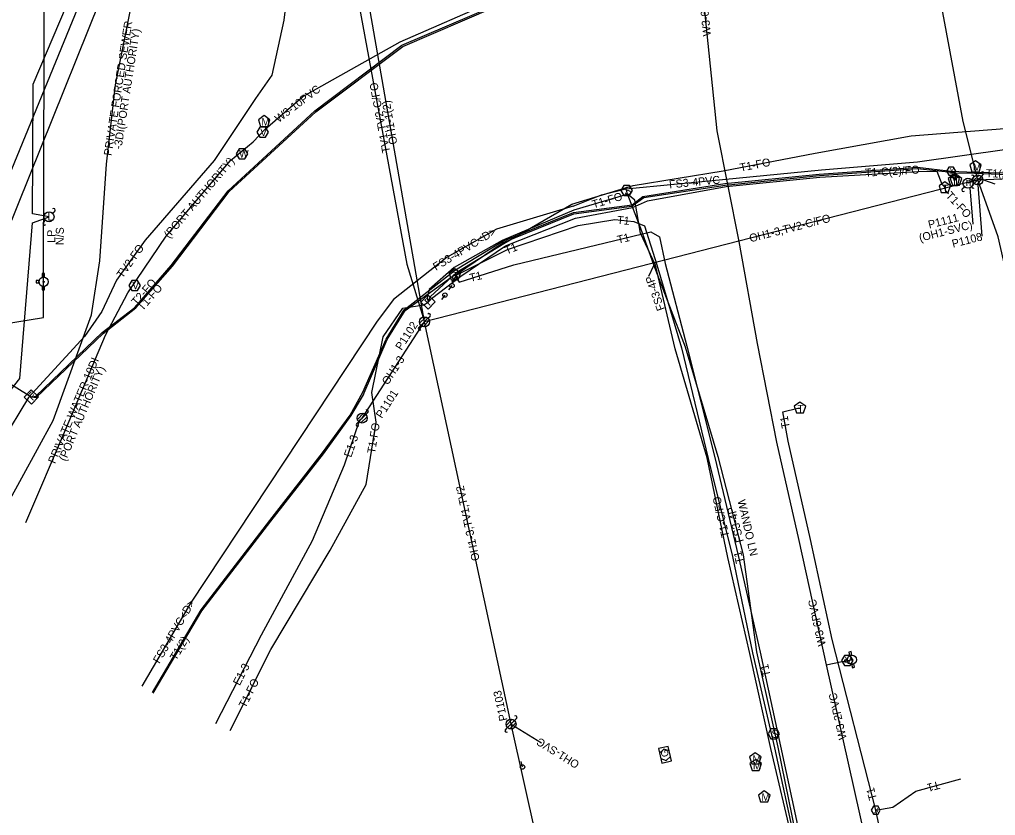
# Model space of a CAD drawing. Extents: x 2336688 to 2352634, y 362473 to 369571.
# Drawn here: x 2345394.9 to 2345882.8, y 366711.7 to 367109.6 of the extents above; entities that cross this region are included whole.
import ezdxf

# ---------------------------------------------------------------- set-up
doc = ezdxf.new("R2010")
doc.units = 0
for name, color, linetype in [('RD_EX_DV_Prop', 7, 'Continuous'), ('RD_EX_DV_TX_Prop', 7, 'Continuous'), ('RD_EX_RW', 7, 'Continuous'), ('RD_EX_RW_TX', 7, 'Continuous'), ('RD_HC_Data_Tic', 7, 'Continuous'), ('RD_PD_CstnLmt', 7, 'Continuous'), ('RD_PD_Final_TrvlWay', 7, 'Continuous'), ('RD_PD_PatLn4', 7, 'Continuous'), ('RD_SHT_ShtClip', 7, 'Continuous'), ('RD_Sketch1', 7, 'Continuous'), ('RD_Sketch2', 7, 'Continuous'), ('RD_Sketch5', 7, 'Continuous'), ('RD_TX_Misc1', 7, 'Continuous')]:
    doc.layers.add(name, color=color, linetype=linetype)

# ---------------------------------------------------------------- blocks, each defined once
blk = doc.blocks.new('GW')
at = {"layer": 'RD_HC_Data_Tic'}
blk.add_line((0, 0), (0, 5), dxfattribs=at)
blk.add_circle((0, 0), 2, dxfattribs=at)

msp = doc.modelspace()

# ---------------------------------------------------------------- linework, layer by layer
at = {"layer": 'RD_EX_DV_TX_Prop'}
for p, q in [((2345876.09, 367001.24), (2345874.09, 367026.87)), ((2345871.56, 367007.24), (2345870.14, 367025.46))]:
    msp.add_line(p, q, dxfattribs=at)
at = {"layer": 'RD_EX_RW_TX'}
msp.add_line((2345399.69, 366921.53), (2345364.16, 366943.34), dxfattribs=at)
for points in [[(2345400.86, 367609.96), (2345400.86, 367580.52), (2345476.19, 367221.38), (2345364.16, 366943.34), (2345117.95, 366720.57)], [(2345560.36, 367158.37), (2345561.17, 367156.84), (2345555.2, 367151.92), (2345529.41, 367128.95), (2345527.05, 367109.15), (2345521, 367081.68), (2345512.82, 367070.16), (2345492.13, 367039.11), (2345457.71, 366999.28), (2345443.39, 366979.23), (2345436.01, 366963.6), (2345427.31, 366951.13), (2345399.42, 366920.61), (2345372.17, 366875.98), (2345340.52, 366834.69)], [(2345400.81, 366920.91), (2345403.21, 366920.71), (2345436.7, 366952.69), (2345453.09, 366965.46), (2345471.44, 366986.29), (2345499.66, 367023.61), (2345543.05, 367063.34), (2345586.52, 367096.12), (2345632.95, 367115.99), (2345683.75, 367128.36), (2345734.17, 367135.46), (2345786.21, 367138.11), (2345835, 367141.95), (2345884.47, 367148.28)], [(2345399.69, 366921.53), (2345400.81, 366920.91), (2345403.09, 366921.35), (2345436.25, 366953.11), (2345452.55, 366965.66), (2345470.76, 366986.63), (2345499.17, 367023.99), (2345542.57, 367063.95), (2345586.06, 367096.71), (2345632.54, 367116.51), (2345683.64, 367129.17), (2345734.05, 367136.11), (2345786.05, 367139.04), (2345834.85, 367142.6), (2345856.07, 367145.42), (2345857.04, 367146.79)], [(2345500.17, 366754.27), (2345520.52, 366794.66), (2345550.15, 366844.34), (2345568.15, 366877.1), (2345573.13, 366908.35), (2345571.01, 366923.07), (2345576.64, 366951.02), (2345586.5, 366965.25), (2345596.98, 366967.01), (2345599.12, 366968.34), (2345600.17, 366970.98), (2345613.47, 366983.28), (2345637.02, 366997.67), (2345671.07, 367017.26), (2345701.71, 367026.64), (2345746.61, 367033.87), (2345792.68, 367042.78), (2345840.6, 367051.43), (2345887.37, 367055.13)], [(2345461.45, 366773.12), (2345485.72, 366814.45), (2345520.05, 366859.13), (2345546.44, 366892.9), (2345560.12, 366911.85), (2345566.57, 366923.25), (2345578.21, 366949.73), (2345587.16, 366964.52), (2345612.86, 366984.47), (2345636.46, 366998.7), (2345671.8, 367013.17), (2345701.1, 367016.89), (2345706.53, 367021.09), (2345747.51, 367027.63), (2345794.71, 367032.18), (2345843.88, 367035.75), (2345860.6, 367033.82), (2345872.36, 367033.23), (2345893.42, 367032.83)], [(2345461.79, 366772.92), (2345486.1, 366814.09), (2345520.53, 366858.85), (2345546.93, 366892.43), (2345560.65, 366911.63), (2345566.89, 366921.96), (2345567.23, 366922.93), (2345578.65, 366949.6), (2345587.63, 366964.05), (2345611.13, 366981.08), (2345612.48, 366981.87), (2345613.41, 366982.24), (2345636.74, 366998.18), (2345672.09, 367012.44), (2345701.07, 367016.24), (2345707.06, 367020.61), (2345747.66, 367026.84), (2345794.76, 367031.59), (2345843.89, 367035.01), (2345862.09, 367033.07), (2345862.66, 367029.98), (2345863.05, 367029.2), (2345863.18, 367029.93), (2345862.88, 367032.97), (2345872.26, 367032.7), (2345893.38, 367031.97)], [(2345599.12, 366968.34), (2345600.85, 366970.06), (2345615.49, 366981.23), (2345637.9, 366996.5), (2345672.85, 367010.22), (2345701.31, 367015.58), (2345708.79, 367018.93), (2345748.08, 367026.1), (2345794.99, 367030.74), (2345843.92, 367033.65), (2345853.44, 367033.69), (2345855.93, 367027.34), (2345856.96, 367026.23), (2345857.46, 367025.46), (2345857.67, 367024.28), (2345859.32, 367022.48)], [(2345860.6, 367033.82), (2345861.81, 367030.13), (2345861.99, 367029.09)], [(2345873.97, 367029.36), (2345874.41, 367030.21), (2345882.47, 367027.46)], [(2345750.74, 366593.81), (2345793.71, 366604.91), (2345793.6, 366606.53), (2345795.31, 366607.4), (2345799.9, 366613.11), (2345800.37, 366616.85), (2345793.67, 366642.96), (2345781.73, 366697.86), (2345770.41, 366745.28), (2345760, 366792.61), (2345749.03, 366840.68), (2345738.69, 366890.47), (2345722.69, 366945), (2345712.84, 366986.7), (2345705.27, 367002.76), (2345702.43, 367019.22), (2345698.82, 367022.22), (2345694.02, 367020.8), (2345671.99, 367014.3), (2345636.25, 366999.09), (2345612.16, 366985.56), (2345599.72, 366974.65), (2345598.65, 366970.42), (2345599.12, 366968.34)], [(2345612.48, 366981.87), (2345613.56, 366981.96), (2345638.84, 366994.67), (2345674.13, 367006.57), (2345692.49, 367009.56), (2345702.05, 367008.67), (2345707.41, 367006.4), (2345713.56, 366986.96), (2345725.76, 366945.42), (2345739.18, 366890.21), (2345751.26, 366841.1), (2345761.25, 366792.95), (2345772.3, 366745.59), (2345783.61, 366693.46), (2345794.68, 366643.14), (2345807.85, 366590.13), (2345818.75, 366543.34)], [(2345612.48, 366981.87), (2345612.77, 366981.03), (2345614.7, 366978.36), (2345642.03, 366986.89), (2345710.46, 367003.43), (2345714.81, 367000.95), (2345717.61, 366987.66), (2345728.58, 366946.26), (2345742.57, 366890.63), (2345754.16, 366841.7), (2345765.23, 366793.37), (2345775.39, 366746.33), (2345786.64, 366693.71), (2345797.72, 366643.63), (2345808.54, 366590.2), (2345821.21, 366544.02)], [(2345856.53, 366551.35), (2345848.37, 366592.23), (2345848.01, 366593.78), (2345854.54, 366595.47), (2345855.72, 366595.54), (2345853.67, 366595.82), (2345847.63, 366594.93), (2345846.69, 366600.45), (2345836.4, 366650.92), (2345822.92, 366714.36), (2345801.14, 366799.7), (2345790.37, 366849.7), (2345779.17, 366898.83), (2345776.52, 366913.54), (2345784.01, 366915.26), (2345785.05, 366915.36)], [(2345822.92, 366714.36), (2345831.44, 366715.85), (2345843.03, 366723.83), (2345865.4, 366730.06)]]:
    msp.add_lwpolyline(points, dxfattribs=at)
for points in [[(2345862.91, 367033.82), (2345861.76, 367035.82), (2345859.45, 367035.82), (2345858.29, 367033.82), (2345859.45, 367031.82), (2345861.76, 367031.82)], [(2345861.99, 367032.09), (2345859.14, 367030.02), (2345860.23, 367026.66), (2345863.76, 367026.66), (2345864.85, 367030.02)], [(2345863.05, 367032.2), (2345860.2, 367030.13), (2345861.29, 367026.78), (2345864.82, 367026.78), (2345865.91, 367030.13)], [(2345857.46, 367028.46), (2345854.6, 367026.39), (2345855.69, 367023.03), (2345859.22, 367023.03), (2345860.31, 367026.39)], [(2345612.48, 366984.87), (2345609.63, 366982.8), (2345610.72, 366979.44), (2345614.24, 366979.44), (2345615.33, 366982.8)], [(2345599.06, 366971.88), (2345595.59, 366968.28), (2345599.19, 366964.81), (2345602.66, 366968.41)], [(2345400.74, 366924.44), (2345397.28, 366920.84), (2345400.88, 366917.38), (2345404.34, 366920.98)], [(2345785.05, 366918.36), (2345782.2, 366916.29), (2345783.29, 366912.94), (2345786.82, 366912.94), (2345787.91, 366916.29)], [(2345825.23, 366714.36), (2345824.07, 366716.36), (2345821.76, 366716.36), (2345820.61, 366714.36), (2345821.76, 366712.36), (2345824.07, 366712.36)]]:
    msp.add_lwpolyline(points, close=True, dxfattribs=at)
at = {"layer": 'RD_HC_Data_Tic'}
for p, q in [((2345871.55, 367028.72), (2345874.62, 367031.78)), ((2345872.2, 367027.6), (2345875.74, 367031.13)), ((2345875.74, 367031.13), (2345876.8, 367032.19)), ((2345866.21, 367024.88), (2345867.27, 367025.94)), ((2345870.81, 367029.47), (2345871.87, 367030.53)), ((2345871.14, 367026.54), (2345872.2, 367027.6)), ((2345873.32, 367026.95), (2345876.38, 367030.01)), ((2345411.42, 367012.73), (2345412.48, 367013.79)), ((2345406.83, 367008.13), (2345407.89, 367009.2)), ((2345594.89, 366957.8), (2345597.95, 366960.86)), ((2345595.54, 366956.68), (2345599.07, 366960.21)), ((2345596.66, 366956.03), (2345599.72, 366959.09)), ((2345599.07, 366960.21), (2345600.13, 366961.27)), ((2345594.48, 366955.61), (2345595.54, 366956.68)), ((2345563.82, 366909.71), (2345566.88, 366912.77)), ((2345564.47, 366908.59), (2345568, 366912.12)), ((2345565.59, 366907.94), (2345568.65, 366911)), ((2345568, 366912.12), (2345569.06, 366913.18)), ((2345563.41, 366907.53), (2345564.47, 366908.59)), ((2345638.18, 366756.75), (2345641.24, 366759.81)), ((2345638.83, 366755.63), (2345642.36, 366759.17)), ((2345639.95, 366754.98), (2345643.01, 366758.05)), ((2345642.36, 366759.17), (2345643.42, 366760.23)), ((2345637.77, 366754.57), (2345638.83, 366755.63))]:
    msp.add_line(p, q, dxfattribs=at)
for centre in [(2345873.97, 367029.36), (2345869.04, 367027.71), (2345409.65, 367010.96), (2345597.31, 366958.44), (2345566.24, 366910.36), (2345640.6, 366757.4)]:
    msp.add_circle(centre, 2.5, dxfattribs=at)
for centre, start, end in [((2345871.34, 367031.06), 315, 135), ((2345876.27, 367032.72), 315, 135), ((2345871.67, 367026.01), 135, 315), ((2345866.74, 367024.35), 135, 315), ((2345411.95, 367014.32), 315, 135), ((2345407.36, 367007.6), 135, 315), ((2345599.6, 366961.8), 315, 135), ((2345595.01, 366955.08), 135, 315), ((2345568.53, 366913.71), 315, 135), ((2345563.94, 366907), 135, 315), ((2345642.89, 366760.76), 315, 135), ((2345638.3, 366754.04), 135, 315)]:
    msp.add_arc(centre, 0.75, start, end, dxfattribs=at)
at = {"layer": 'RD_PD_Final_TrvlWay'}
for points in [[(2345391.05, 367609.96), (2345391.05, 367588.26), (2345470.9, 367229.85), (2345354.8, 366946.71), (2345105.35, 366734.78)], [(2345370.88, 366899.63), (2345394.98, 366930.11), (2345401.39, 367007.89), (2345409.65, 367010.96), (2345401.4, 367012.45), (2345401.49, 367040.33), (2345401.67, 367077.29), (2345441.14, 367170.24)], [(2345493.08, 366757.65), (2345515.92, 366802), (2345541.44, 366849.18), (2345557.44, 366887), (2345565.1, 366909.55), (2345566.24, 366910.36)]]:
    msp.add_lwpolyline(points, dxfattribs=at)
at = {"layer": 'RD_SHT_ShtClip'}
for p, q in [((2345597.31, 366958.44), (2345562.51, 367157.67)), ((2345873.97, 367029.36), (2346156.71, 367042.77)), ((2345873.97, 367029.36), (2345597.31, 366958.44)), ((2345873.97, 367029.36), (2345869.04, 367027.71)), ((2345566.24, 366910.36), (2345597.31, 366958.44)), ((2345640.6, 366757.4), (2345597.31, 366958.44)), ((2345680.37, 366580.27), (2345640.6, 366757.4)), ((2345640.6, 366757.4), (2345655.83, 366747.95))]:
    msp.add_line(p, q, dxfattribs=at)
for points in [[(2345873.97, 367029.36), (2345866.69, 367058.52), (2345835.13, 367227.45), (2345831.39, 367257.27)], [(2345560.36, 367158.37), (2345562.49, 367128.3), (2345588.55, 366987.28), (2345597.31, 366958.44)], [(2345936.7, 366754.94), (2345933.52, 366784.99), (2345884.16, 367000.92), (2345873.97, 367029.36)]]:
    msp.add_lwpolyline(points, dxfattribs=at)
at = {"layer": 'RD_Sketch1'}
msp.add_line((2345709.53, 366981.32), (2345711.96, 366986.54), dxfattribs=at)
at = {"layer": 'RD_Sketch2'}
for p, q in [((2345406.29, 366982.54), (2345406.28, 366980.68)), ((2345407.44, 366982.54), (2345406.29, 366982.54)), ((2345407.44, 366980.72), (2345407.44, 366982.54)), ((2345404.72, 366979.1), (2345403.22, 366979.11)), ((2345403.22, 366979.11), (2345403.22, 366977.95)), ((2345403.22, 366977.95), (2345404.69, 366977.95)), ((2345406.27, 366976.26), (2345406.26, 366974.46)), ((2345406.26, 366974.46), (2345407.42, 366974.46)), ((2345407.42, 366974.46), (2345407.42, 366976.21)), ((2345810.61, 366793.68), (2345809.48, 366793.43)), ((2345809.48, 366793.43), (2345809.89, 366791.61)), ((2345811.01, 366791.91), (2345810.61, 366793.68)), ((2345808.72, 366789.72), (2345807.26, 366789.39)), ((2345807.26, 366789.39), (2345807.51, 366788.27)), ((2345807.51, 366788.27), (2345808.95, 366788.59)), ((2345810.87, 366787.29), (2345811.26, 366785.54)), ((2345812.39, 366785.79), (2345812, 366787.51)), ((2345811.26, 366785.54), (2345812.39, 366785.79))]:
    msp.add_line(p, q, dxfattribs=at)
for points in [[(2345109.82, 366912.24), (2345406.89, 366960.68), (2345406.94, 366978.47), (2345408.67, 367610.14)], [(2345398.01, 366858.08), (2345417.9, 366904.52), (2345437.85, 366951.84), (2345449.04, 366972.91), (2345453.48, 366979.61), (2345468.15, 367001.19), (2345500.41, 367039.08), (2345511.67, 367048.37), (2345517.71, 367054.69), (2345536.56, 367071.08), (2345585.14, 367098.45), (2345633.32, 367119.57), (2345683.1, 367133.89), (2345734.03, 367142.31), (2345784.94, 367146.49), (2345833.73, 367148.15), (2345883.62, 367150.82)], [(2345734.3, 367142.33), (2345734.6, 367138.65), (2345736.14, 367125.25), (2345743.53, 367053.85), (2345754.56, 366998.53), (2345763.65, 366947.65), (2345773.38, 366898.37), (2345784.57, 366849.11), (2345798.12, 366787.04), (2345817.62, 366699.96), (2345828.5, 366650.59), (2345839.82, 366600.83), (2345850.62, 366551.62)], [(2345798.12, 366787.04), (2345805.39, 366788.58), (2345809.76, 366789.38), (2345811.03, 366789.6)]]:
    msp.add_lwpolyline(points, dxfattribs=at)
for points in [[(2345517.2, 367061.57), (2345514.3, 367059.46), (2345515.41, 367056.05), (2345518.99, 367056.05), (2345520.1, 367059.46)], [(2345519.33, 367053.2), (2345517.88, 367055.7), (2345515, 367055.7), (2345513.55, 367053.2), (2345515, 367050.7), (2345517.88, 367050.7)], [(2345508.97, 367042.41), (2345507.53, 367044.9), (2345504.64, 367044.9), (2345503.2, 367042.41), (2345504.64, 367039.91), (2345507.53, 367039.91)], [(2345872.81, 367038.97), (2345869.91, 367036.86), (2345871.02, 367033.45), (2345874.61, 367033.45), (2345875.71, 367036.86)], [(2345455.33, 366976.65), (2345453.89, 366979.15), (2345451, 366979.15), (2345449.56, 366976.65), (2345451, 366974.15), (2345453.89, 366974.15)], [(2345811.62, 366789.24), (2345810.17, 366791.74), (2345807.29, 366791.74), (2345805.84, 366789.24), (2345807.29, 366786.74), (2345810.17, 366786.74)], [(2345762.7, 366743.07), (2345759.8, 366740.96), (2345760.91, 366737.55), (2345764.49, 366737.55), (2345765.6, 366740.96)], [(2345762.93, 366739.76), (2345760.03, 366737.65), (2345761.14, 366734.24), (2345764.72, 366734.24), (2345765.83, 366737.65)], [(2345767.19, 366724.03), (2345764.29, 366721.93), (2345765.39, 366718.52), (2345768.98, 366718.52), (2345770.09, 366721.93)]]:
    msp.add_lwpolyline(points, close=True, dxfattribs=at)
for centre, radius in [((2345406.94, 366978.47), 2.31), ((2345406.94, 366978.47), 0.289), ((2345811.03, 366789.6), 2.31), ((2345811.03, 366789.6), 0.289)]:
    msp.add_circle(centre, radius, dxfattribs=at)
for centre, start, end in [((2345406.94, 366978.47), 164.064, 193.0312), ((2345406.94, 366978.47), 77.5034, 106.4797), ((2345406.94, 366978.47), 253.1571, 282.1335), ((2345811.03, 366789.6), 90.4016, 119.378), ((2345811.03, 366789.6), 176.9622, 205.9294), ((2345811.03, 366789.6), 266.0554, 295.0317)]:
    msp.add_arc(centre, 2.31, start, end, dxfattribs=at)
at = {"layer": 'RD_Sketch5'}
for points in [[(2345388.31, 366866.23), (2345411.68, 366909.13), (2345430.85, 366961.88), (2345435.05, 366988.91), (2345438.45, 367037.33), (2345442.85, 367076.95), (2345451.04, 367117.69)], [(2345671.65, 367016.28), (2345685.91, 367021.93), (2345698.01, 367025), (2345746.34, 367029.53), (2345795.81, 367034.45), (2345843.73, 367038.37), (2345888.51, 367044.73), (2345943.3, 367049.45), (2346003.21, 367051.06), (2346044.44, 367048.09), (2346104.33, 367049.8), (2346147.49, 367056.12), (2346190.02, 367059.03), (2346247.96, 367065.62), (2346294.65, 367066.48), (2346342.24, 367070.89), (2346392.92, 367073.62), (2346445.33, 367080.3)], [(2345698.01, 367025), (2345698.55, 367022.93), (2345705.27, 367005.26), (2345711.96, 366986.54), (2345727.6, 366946), (2345743.93, 366891.21), (2345756.59, 366841.99), (2345763.32, 366793.48), (2345773.98, 366745.9), (2345784.68, 366693.55), (2345796.23, 366643.51), (2345807.18, 366590.01), (2345819.85, 366543.64)], [(2345671.65, 367016.28), (2345633.43, 367004.74), (2345608.63, 366990.82), (2345581.94, 366969.69), (2345573.77, 366958.77), (2345480.4, 366817.86), (2345456.01, 366776.32)]]:
    msp.add_lwpolyline(points, dxfattribs=at)
for points in [[(2345701.36, 367024.03), (2345699.91, 367026.53), (2345697.02, 367026.53), (2345695.58, 367024.03), (2345697.02, 367021.53), (2345699.91, 367021.53)], [(2345774.9, 366752.52), (2345773.46, 366755.02), (2345770.57, 366755.02), (2345769.12, 366752.52), (2345770.57, 366750.02), (2345773.46, 366750.02)], [(2345714.36, 366745.16), (2345715.96, 366737.89), (2345720.84, 366738.97), (2345719.24, 366746.24)], [(2345716.98, 366744.88), (2345714.85, 366742.94), (2345715.47, 366740.12), (2345718.22, 366739.25), (2345720.35, 366741.19), (2345719.73, 366744.01)]]:
    msp.add_lwpolyline(points, close=True, dxfattribs=at)

# ---------------------------------------------------------------- block references
at = {"layer": 'RD_HC_Data_Tic'}
for p, xscale, yscale, rotation in [((2345612.59, 366980.61), 0.5546771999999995, 0.5546771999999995, 145.4615776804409), ((2345611.09, 366976.57), 0.5546771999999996, 0.5546771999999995, 142.58503020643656), ((2345607.56, 366971.82), 0.5546771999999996, 0.5546771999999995, 142.58503020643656), ((2345646.33, 366735.97), 0.5546771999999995, 0.5546771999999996, 14.68368123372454)]:
    msp.add_blockref('GW', p, dxfattribs=dict(at, xscale=xscale, yscale=yscale, rotation=rotation))

# ---------------------------------------------------------------- texts
at = {"layer": 'RD_EX_DV_Prop'}
for rotation, p in [(71.2379, (2345560.71, 366890.4)), (62.7502, (2345504.95, 366776.34))]:
    msp.add_text('E1-3', height=4, rotation=rotation, dxfattribs=at).set_placement(p)
at = {"layer": 'RD_EX_DV_TX_Prop'}
for s, rotation, p in [('P1111', 14.3778, (2345849.7, 367004.99)), ('(OH1-SVC)', 14.3778, (2345845.14, 366998.44)), ('LP', 89.8269, (2345412.75, 366997.96)), ('N/S', 89.8269, (2345417.03, 366996.81)), ('P1108', 14.3778, (2345861.58, 366995.45)), ('P1102', 57.134, (2345585.85, 366943.93)), ('P1101', 57.134, (2345576.06, 366909.88)), ('P1103', 102.1519, (2345638.83, 366759.38))]:
    msp.add_text(s, height=4, rotation=rotation, dxfattribs=at).set_placement(p)
at = {"layer": 'RD_EX_RW'}
for s, rotation, p in [('T1-FO', 10.9532, (2345755.4, 367033.53)), ('T1-C(2)/FO', 3.3789, (2345817.65, 367030.99)), ('T1(2)', 358.0156, (2345877.92, 367030.77)), ('T1-FO', 16.4364, (2345681.83, 367015.12)), ('T1-FO', 312.7547, (2345857.68, 367021.3)), ('T1', 354.6878, (2345693.51, 367007.45)), ('T1', 13.5856, (2345694.21, 366997.45)), ('TV2-FO', 54.4639, (2345446.35, 366979.93)), ('T1', 22.4046, (2345638.46, 366991.98)), ('T1', 13.5856, (2345620.36, 366978.41)), ('T2-FO', 48.6258, (2345453.42, 366966.25)), ('T1-FO', 48.6258, (2345456.46, 366963.62)), ('T1', 100.2126, (2345779.99, 366905.55)), ('T1-FO', 80.9523, (2345572.62, 366892.4)), ('T1-C/FO', 102.6774, (2345749.8, 366851.18)), ('T1', 102.9011, (2345757.03, 366838.12)), ('T1(2)', 59.4351, (2345473.25, 366788.86)), ('T1', 102.1936, (2345770.39, 366781.6)), ('T1-FO', 63.2701, (2345507.87, 366765.09)), ('T1', 195.5492, (2345854.26, 366729.03)), ('T1', 104.3143, (2345823.56, 366719.94))]:
    msp.add_text(s, height=4, rotation=rotation, dxfattribs=at).set_placement(p)
at = {"layer": 'RD_EX_RW_TX'}
for s, height, p in [('X', 3, (2345859.66, 367032.32)), ('T', 3.75, (2345861.82, 367026.98)), ('T', 3.75, (2345856.23, 367023.23)), ('T', 3.75, (2345860.77, 367026.86)), ('T', 3.75, (2345611.25, 366979.64)), ('T', 3.75, (2345783.83, 366913.14)), ('X', 3, (2345821.97, 366712.86))]:
    msp.add_text(s, height=height, dxfattribs=at).set_placement(p)
for p in [(2345599.78, 366966.14), (2345401.46, 366918.71)]:
    msp.add_text('F', height=4, rotation=46.0595, dxfattribs=at).set_placement(p)
at = {"layer": 'RD_HC_Data_Tic'}
for s, p in [('m', (2345867.86, 367026.38)), ('L', (2345408.84, 367009.03))]:
    msp.add_text(s, height=4, rotation=360, dxfattribs=at).set_placement(p)
at = {"layer": 'RD_PD_CstnLmt'}
for s, rotation, p in [('W3-6PVC', 95.9066, (2345740.62, 367101.44)), ('W3-10PVC', 37.0199, (2345524.39, 367057.83)), ('(PORT AUTHORITY)', 49.5935, (2345469.7, 366999.92)), ('PRIVATE WATER-10DI', 67.1316, (2345412.68, 366887.26)), ('(PORT AUTHORITY)', 67.1316, (2345417.98, 366888.49)), ('W3-6PVC', 102.3181, (2345798.03, 366796.86)), ('W3-2PVC', 102.6202, (2345808.44, 366750.1))]:
    msp.add_text(s, height=4, rotation=rotation, dxfattribs=at).set_placement(p)
at = {"layer": 'RD_PD_PatLn4'}
for s, rotation, p in [('TV1,TV2-C/FO', 100.4703, (2345580.24, 367043.27)), ('OH1-1(2)', 99.9068, (2345583.79, 367047.44)), ('OH1-3,TV2-C/FO', 14.3778, (2345760.32, 366998.17)), ('OH1-3', 57.134, (2345579.09, 366926.56)), ('OH1-3,TV1,TV2', 102.1519, (2345624.98, 366839.42)), ('OH1-SVC', 148.1924, (2345675.19, 366738.3))]:
    msp.add_text(s, height=4, rotation=rotation, dxfattribs=at).set_placement(p)
at = {"layer": 'RD_Sketch1'}
for s, rotation, p in [('PRIVATE FORCED SEWER', 81.2207, (2345440.91, 367041.26)), ('-3DI(PORT AUTHORITY)', 81.2207, (2345445.86, 367044.5)), ('FS3-4PVC', 5.3578, (2345719.83, 367025.15)), ('FS3-4PVC<D>', 31.4694, (2345603.1, 366983.86)), ('FS3-4P', 109.6647, (2345717.55, 366964.82)), ('FS3-4P', 104.4207, (2345757.04, 366848.77)), ('FS3-4PVC<D>', 59.5819, (2345464.81, 366787.35))]:
    msp.add_text(s, height=4, rotation=rotation, dxfattribs=at).set_placement(p)
at = {"layer": 'RD_Sketch2'}
for s, p in [('M', (2345515.83, 367056.53)), ('V', (2345515.23, 367051.32)), ('W', (2345504.7, 367040.53)), ('M', (2345871.44, 367033.93)), ('V', (2345451.24, 366974.77)), ('V', (2345807.52, 366787.37)), ('M', (2345761.33, 366738.03)), ('M', (2345761.56, 366734.72)), ('M', (2345765.82, 366718.99))]:
    msp.add_text(s, height=3.75, dxfattribs=at).set_placement(p)
at = {"layer": 'RD_Sketch5'}
for p in [(2345697.24, 367022.03), (2345770.78, 366750.52)]:
    msp.add_text('S', height=4, dxfattribs=at).set_placement(p)
msp.add_text('G', height=3.53, rotation=102.3992, dxfattribs=at).set_placement((2345719.56, 366741.38))
at = {"layer": 'RD_TX_Misc1'}
msp.add_text('WANDO LN', height=4, rotation=282.8007, dxfattribs=at).set_placement((2345753.82, 366869.15))

doc.saveas('drawing.dxf')
